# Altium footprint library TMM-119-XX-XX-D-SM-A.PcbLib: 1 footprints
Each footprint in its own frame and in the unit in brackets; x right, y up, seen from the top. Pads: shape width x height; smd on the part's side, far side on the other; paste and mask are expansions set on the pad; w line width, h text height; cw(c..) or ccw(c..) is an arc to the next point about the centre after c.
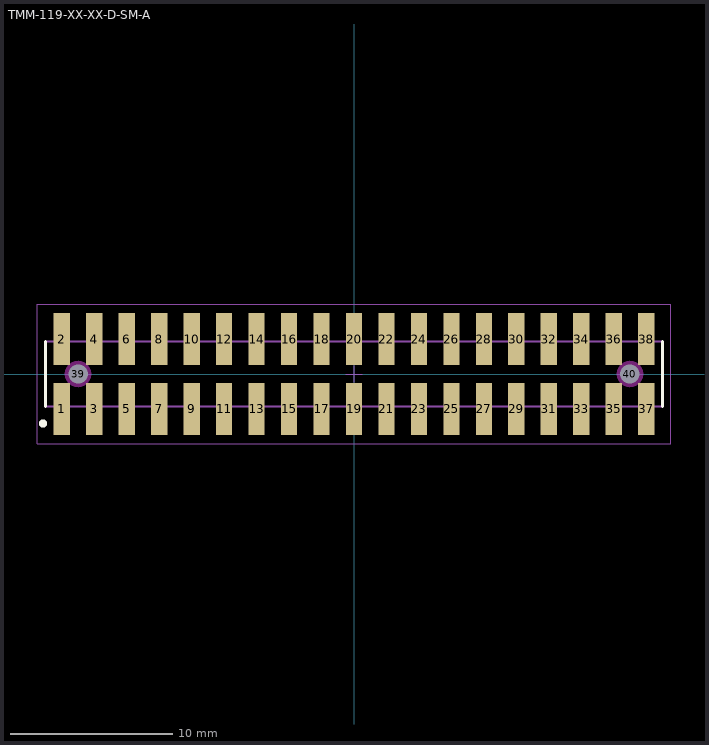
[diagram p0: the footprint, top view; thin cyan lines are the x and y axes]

## TMM-119-XX-XX-D-SM-A [mm] "2.00mm pitch, 38 pin, terminal strip; double row, w/alignment pins, SMT"
height 2.77
pads (40):
  rect 1x3.2 smd mask+0: 1(-18,-2.15) 2(-18,2.15) 3(-16,-2.15) 4(-16,2.15) 5(-14,-2.15) 6(-14,2.15) 7(-12,-2.15) 8(-12,2.15) 9(-10,-2.15) 10(-10,2.15) 11(-8,-2.15) 12(-8,2.15) 13(-6,-2.15) 14(-6,2.15) 15(-4,-2.15) 16(-4,2.15) 17(-2,-2.15) 18(-2,2.15) 19(0,-2.15) 20(0,2.15) 21(2,-2.15) 22(2,2.15) 23(4,-2.15) 24(4,2.15) 25(6,-2.15) 26(6,2.15) 27(8,-2.15) 28(8,2.15) 29(10,-2.15) 30(10,2.15) 31(12,-2.15) 32(12,2.15) 33(14,-2.15) 34(14,2.15) 35(16,-2.15) 36(16,2.15) 37(18,-2.15) 38(18,2.15)
  round 1 hole 1.2 unplated mask+0: 39(-17,0) 40(17,0)
Top Overlay:
  circle w0.25: c-19.15,-3.05 r0.125
  lines w0.2: -19,-2 -19,2 ; 19,-2 19,2
Keep-Out Layer:
  pour cut-out: -16.193,0 -16.221,0.209 -16.301,0.403 -16.429,0.571 -16.597,0.699 -16.791,0.779 -17,0.807 -17.209,0.779 -17.403,0.699 -17.571,0.571 -17.699,0.403 -17.779,0.209 -17.807,0 -17.779,-0.209 -17.699,-0.403 -17.571,-0.571 -17.403,-0.699 -17.209,-0.779 -17,-0.807 -16.791,-0.779 -16.597,-0.699 -16.429,-0.571 -16.301,-0.403 -16.221,-0.209
  pour cut-out: 17.807,0 17.779,0.209 17.699,0.403 17.571,0.571 17.403,0.699 17.209,0.779 17,0.807 16.791,0.779 16.597,0.699 16.429,0.571 16.301,0.403 16.221,0.209 16.193,0 16.221,-0.209 16.301,-0.403 16.429,-0.571 16.597,-0.699 16.791,-0.779 17,-0.807 17.209,-0.779 17.403,-0.699 17.571,-0.571 17.699,-0.403 17.779,-0.209
Mechanical 12:
  lines w0.001: -19,-2 19,-2 19,2 -19,2 -19,-2
Mechanical 13:
  lines w0.1: -19,-2 19,-2 19,2 -19,2 -19,-2
  text ".Designator" at 0,-0.127 h1.52
Mechanical 15:
  lines w0.05: -0.5,0 0.5,0 ; 0,-0.5 0,0.5 ; -19.5,-4.3 19.5,-4.3 19.5,4.3 -19.5,4.3 -19.5,-4.3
